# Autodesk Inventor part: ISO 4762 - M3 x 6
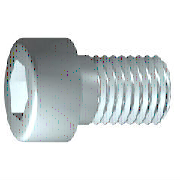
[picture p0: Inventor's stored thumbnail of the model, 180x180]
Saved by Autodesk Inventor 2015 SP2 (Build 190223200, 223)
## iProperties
IsCustomPart: 0
Created: 2012-02
Part Number: ISO 4762 - M3 x 6
Material: Edelstahl, 440C
Description: Innensechskantschraube
Document SubType Name: Modeling
Standard: ISO 4762
Designer: rYan
Standard Revision: 1998
Standards Organization: DIN
Language: de-DE
Size Designation: M3 x 6
Categories: <MemberInstance><Categories><Category DisplayName="Verbindungselemente" InternalName="e4da775c-781d-43d5-af7c-5136215cf5a6" Mnemonic="FSTN"><Category DisplayNam
Density: 7.75 g/cm^3
Appearance: Halbpoliert
Author: rYan
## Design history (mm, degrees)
sketch "Skizze1"
  geometry: L1 (-0.867, 0)-(6, 0); L2 (6, 0)-(6, 1.5); L3 (6, 1.5)-(1.25, 1.5); L4 (1.25, 1.5)-(0.943, 1.5); L5 (0.943, 1.5)-(0, 1.5); L6 (0, 1.5)-(0, 2.75); L7 (0, 2.75)-(-3, 2.75); L8 (-3, 2.75)-(-3, 1.443); L9 (-3, 1.443)-(-1.7, 1.443); L10 (-1.7, 1.443)-(-0.867, 0); L11 (-4.8, 0)-(7.8, 0) reference; L12 (0, -0.55)-(0, 3.3) reference; L13 (1.25, 1.5)-(0, 1.5)
  constraints: 22 end point, 6 parallel, 2 collinear, 2 perpendicular, 1 horizontal, 1 point on line
  dimensions: "d1" = 4.75 distance from line of L3.end L2 (= GEL); "d2" = 0.30683 distance of L4.end L3.end (computed from GAL); "d3" = 3 distance between parallel lines of L8 L6 (= KOH); "d4" = 1.3 distance of L8.end L9.end (= INTI); "d5" = 60 deg angle of L10 L1; "d6" = 3 diameter of L3 L1 (= GD); "d7" = 3 diameter of L5 L1 (= BDM); "d8" = 2.88675 diameter of L9 L1 (= 1.1547 x SW); "d9" = 5.5 diameter of L7 L1 (= KOD); "d26" = 6 distance between parallel lines of L12 L2 (= NLG)
revolve "Körper" sketch "Skizze1" stored, may be unused: angle "d10" = 90 deg
sketch "Skizze2"
  geometry: L1 (0, -3.85)-(0, 3.85) reference; L2 (-3.85, 0)-(3.85, 0) reference; L3 (1.443, 0)-(0.722, -1.25); L4 (0.722, -1.25)-(-0.722, -1.25); L5 (-0.722, -1.25)-(-1.443, 0); L6 (-1.443, 0)-(-0.722, 1.25); L7 (-0.722, 1.25)-(0.722, 1.25); L8 (0.722, 1.25)-(1.443, 0); 2 further points
  constraints: 12 end point, 1 coincident, 1 horizontal alignment, 1 point on line, 12 other
extrude "Loch" join sketch "Skizze2" stored distance "d11" = 10; taper "d12" = 0 deg
workplane "Work Plane1"
fillet "Fillet2" dims "d30" = 0.1 (= R)
body "Solid1"
fillet "Rundung1" dims "d17" = 0.3 (= RR)
feature "Gewinde" dims "d13" = 4.75 (= GEL), "d14" = 0
chamfer "Fase1" distance "d15" = 0.30673 (= -0.5 x SPD + 0.5 x GD); stored, may be unused: second distance "d16" = 0.30673 (= GUL), angle "d27" = 45 deg
other parameters: "GD" = 3 [user parameter; used in 2 equation terms], "NLG" = 6 [user parameter; used in 1 equation term], "GEL" = 4.75 [user parameter; used in 2 equation terms], "KOD" = 5.5 [user parameter; used in 1 equation term], "KOH" = 3 [user parameter; used in 1 equation term], "INTI" = 1.3 [user parameter; used in 1 equation term], "GAL" = 0.30673 (= 0.61345 x PTC) [user parameter; used in 1 equation term], "GUL" = 0.30673 (= 0.61345 x PTC) [user parameter; used in 1 equation term], "BDM" = 3 (= NND) [user parameter; used in 1 equation term], "SW" = 2.5 [user parameter; used in 2 equation terms], "RR" = 0.3 [user parameter; used in 1 equation term], "SPD" = 2.38655 (= NND - 1.2269 x PTC) [user parameter; used in 1 equation term], "d19" = 0, "d28" = 0, "d29" = 0, "R" = 0.1 [user parameter; used in 1 equation term], "TOA" = 30 deg [user parameter], "GD1" = 2.38655 (= THREADDIA - 1.2269 x PTC) [user parameter], "THREADDIA" = 3 [user parameter; used in 1 equation term], "FAWI" = 45 deg [user parameter], "PTC" = 0.5 [user parameter; used in 5 equation terms], "NND" = 3 [user parameter; used in 2 equation terms], "E0" = 2.8875 (= 1.155 x SW) [user parameter]
